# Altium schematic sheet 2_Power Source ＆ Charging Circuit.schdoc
size 441 x 411 mm
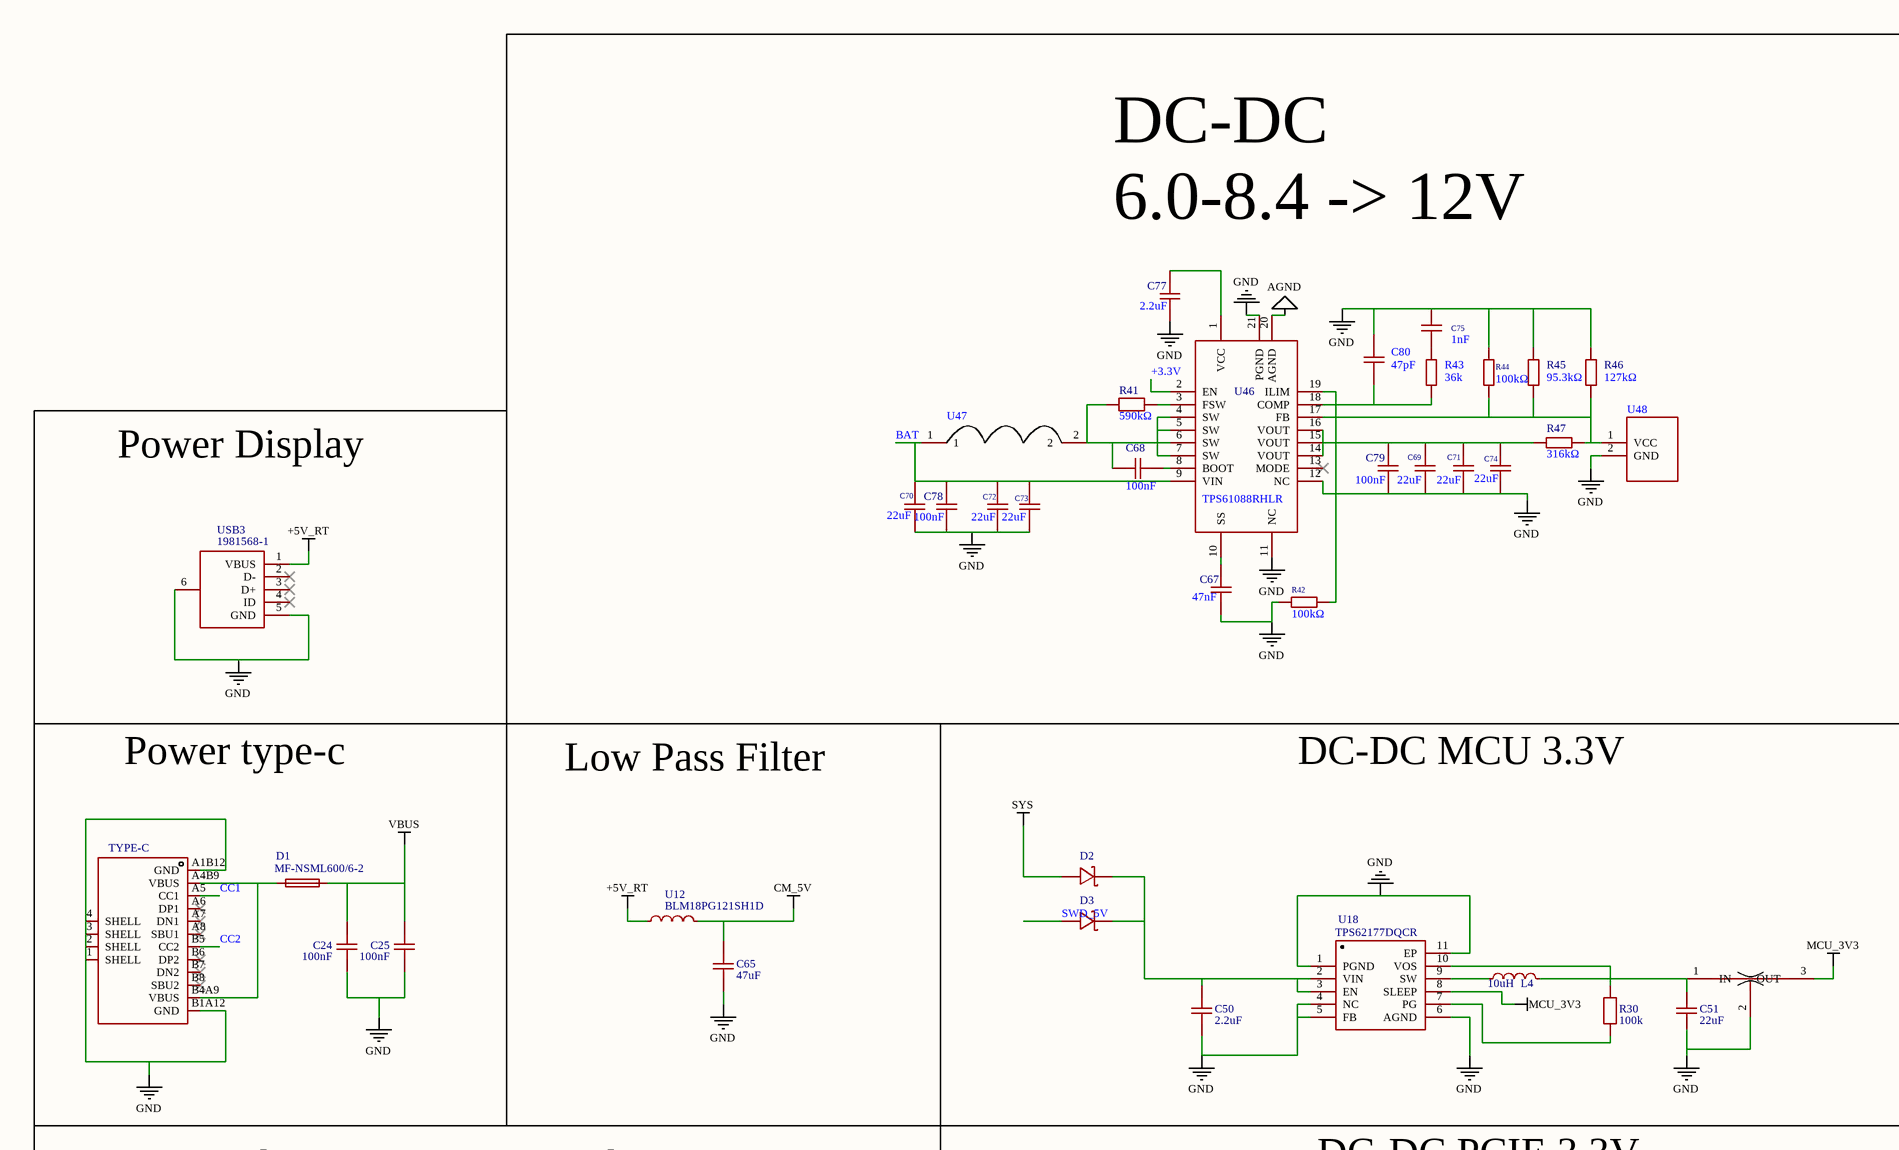
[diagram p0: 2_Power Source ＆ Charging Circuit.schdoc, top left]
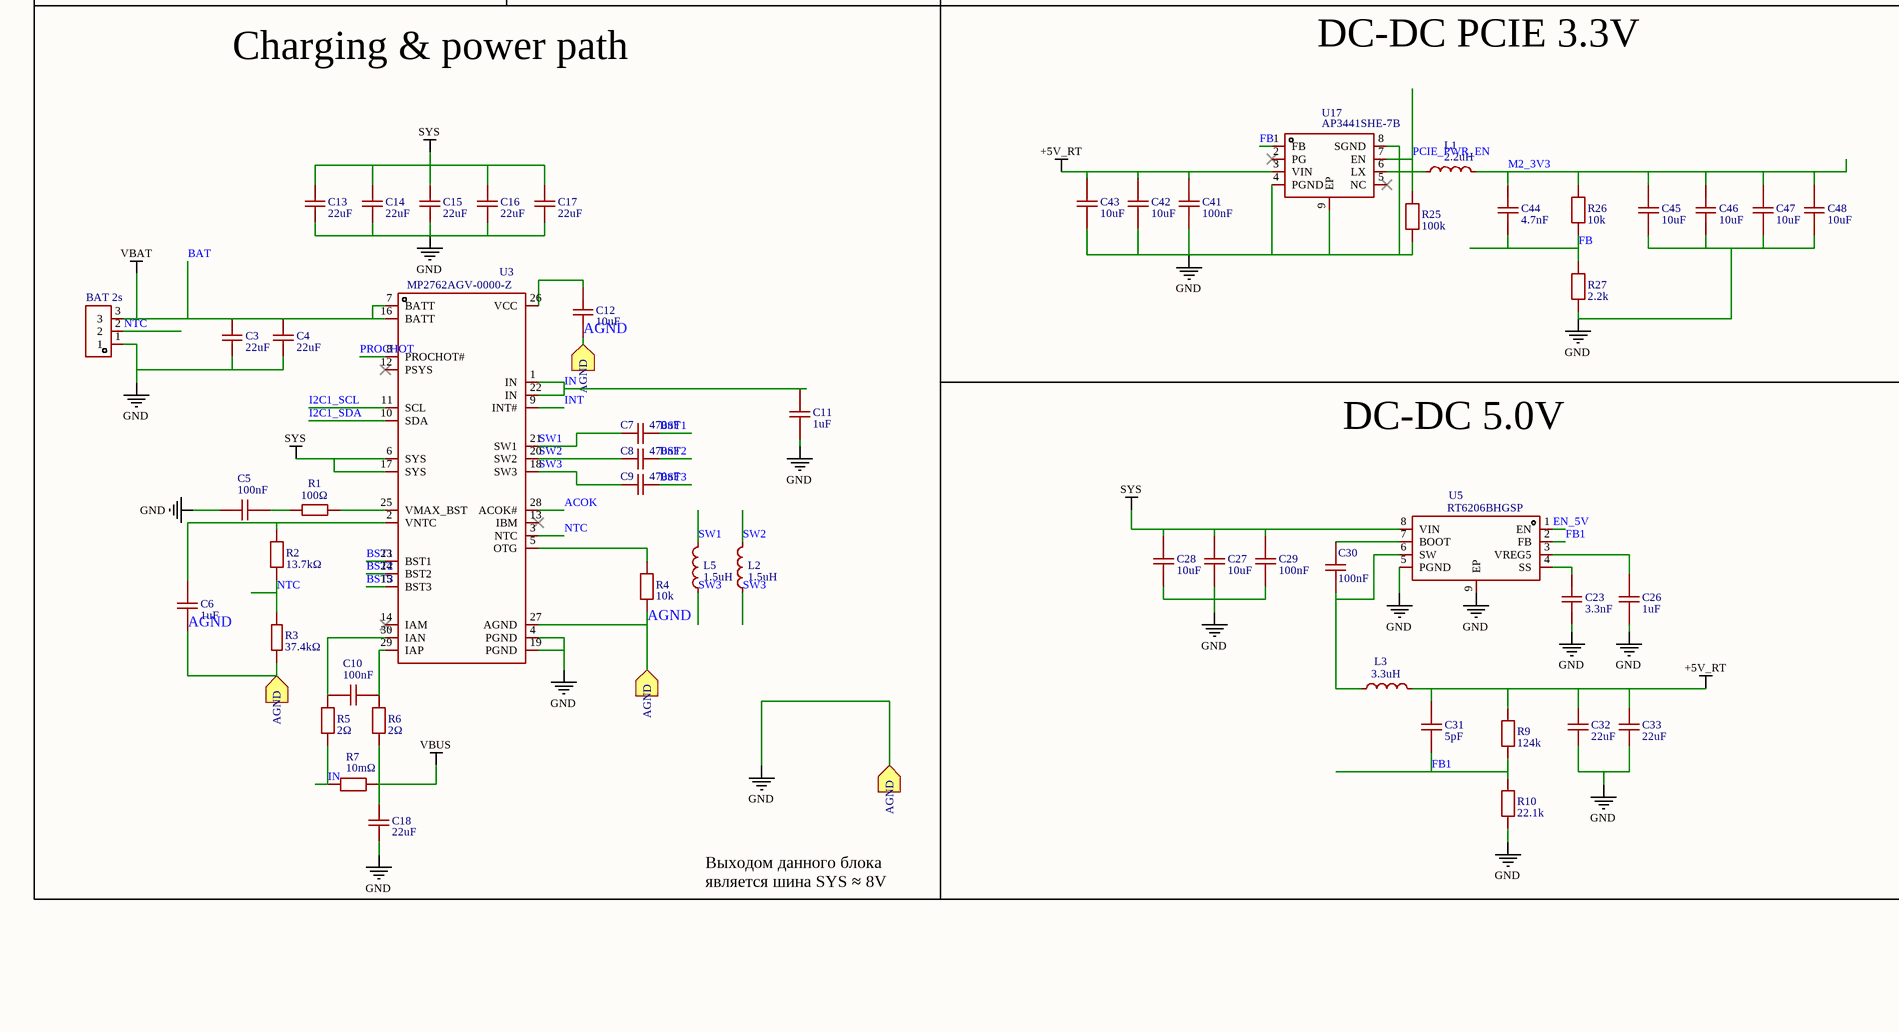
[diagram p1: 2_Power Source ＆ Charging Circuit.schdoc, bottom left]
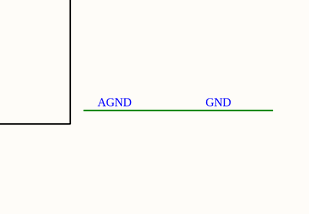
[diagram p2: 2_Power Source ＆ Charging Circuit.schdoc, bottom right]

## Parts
C3  22uF  [C0805]
C4  22uF  [C0805]
C5  100nF  [C0603]
C6  1uF  [C0603]
C7  470nF  [C0603]
C8  470nF  [C0603]
C9  470nF  [C0603]
C10  100nF  [C0603]
C11  1uF  [C0603]
C12  10uF  [C0603]
C13  22uF  [C0805]
C14  22uF  [C0805]
C15  22uF  [C0805]
C16  22uF  [C0805]
C17  22uF  [C0805]
C18  22uF  [C0805]
C23  3.3nF  [C0603]
C24  100nF  [C0603]
C25  100nF  [C0603]
C26  1uF  [C0603]
C27  10uF  [C0603]
C28  10uF  [C0603]
C29  100nF  [C0603]
C30  100nF  [C0603]
C31  5pF  [C0603]
C32  22uF  [C0805]
C33  22uF  [C0805]
C41  100nF  [C0603]
C42  10uF  [C0603]
C43  10uF  [C0603]
C44  4.7nF  [C0603]
C45  10uF  [C0603]
C46  10uF  [C0603]
C47  10uF  [C0603]
C48  10uF  [C0603]
C50  2.2uF  [C0603]
C51  22uF  [C0805]
C63  -  [FILTER-SMD_3P-L1.6-W0.8-L_NFM18CC223R1C3D]  (value not drawn)
C65  47uF  [C0603]
C67  47nF  [C0603]
C68  100nF  [C0603]
C69  22uF  [C0805]
C70  22uF  [C0805]
C71  22uF  [C0805]
C72  22uF  [C0805]
C73  22uF  [C0805]
C74  22uF  [C0805]
C75  1nF  [C0603]
C77  2.2uF  [C0402]
C78  100nF  [C0603]
C79  100nF  [C0603]
C80  47pF  [C0603]
D1  MF-NSML600/6-2  [F1206]
D2  BAT60AE6327HTSA1  [SOD-323_L1.8-W1.3-LS2.5-RD]  (value not drawn)
D3  BAT60AE6327HTSA1  [SOD-323_L1.8-W1.3-LS2.5-RD]  (value not drawn)
L1  2.2uH  [IND-SMD_L3.0-W3.0_IHLP-1212BZ]
L2  1.5uH  [IND-SMD_L5.5-W5.2]
L3  3.3uH  [IND-SMD_L6.5-W6.5_IHLP-2525]
L4  10uH  [IND-SMD_L4.0-W4.0_VLCF4020]
L5  1.5uH  [IND-SMD_L5.5-W5.2]
R1  100Ω  [R0603]
R2  13.7kΩ  [R0603]
R3  37.4kΩ  [R0603]
R4  10k  [R0603]
R5  2Ω  [R0603]
R6  2Ω  [R0603]
R7  10mΩ  [R1206]
R9  124k  [R0603]
R10  22.1k  [R0603]
R25  100k  [R0603]
R26  10k  [R0603]
R27  2.2k  [R0603]
R30  100k  [R0603]
R41  590kΩ  [R0402]
R42  100kΩ  [R0603]
R43  36k  [R0603]
R44  100kΩ  [R0603]
R45  95.3kΩ  [R0603]
R46  127kΩ  [R0603]
R47  316kΩ  [R0603]
U2  BAT 2s  [CONN-TH_XH2.54-3P]
U3  MP2762AGV-0000-Z  [QFN-30_L5.0-W4.0-P0.50-TL_MP2762A]
U5  RT6206BHGSP  [SOP-8_L4.9-W3.9-P1.27-LS6.0-BL-EP-2]
U12  BLM18PG121SH1D  [L0603]
U17  AP3441SHE-7B  [DFN2020-8_L2.0-W2.0-P0.50-BL-EP]
U18  TPS62177DQCR  [WSON-10_L3.0-W2.0-P0.50-BL-EP]
U44  TYPE-C  [USB-C-SMD_TYPE-C16PIN-SHOUHAN]
U46  TPS61088RHLR  [VQFN-20_L4.6-W3.6-P0.50-BL]
U47  (no value)  [CDCSAB0420-1R5M]
U48  (no value)  [DS-201]
USB3  1981568-1  [MICRO-USB-SMD_1981568-1]

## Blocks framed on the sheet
Power Display: USB3
Power type-c: C24 C25 D1 U44
Low Pass Filter: C65 U12
DC-DC MCU 3.3V: C50 C51 C63 D2 D3 L4 R30 U18
Charging & power path: C3-C18 L2 L5 R1-R7 U2 U3
DC-DC PCIE 3.3V: C41-C48 L1 R25-R27 U17
DC-DC 5.0V: C23 C26-C33 L3 R9 R10 U5

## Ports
AGND (in)

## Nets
+5V_RT: C31.2 C32.2 C33.2 C41.2 C42.2 C43.2 L3.2 R9.2 U12.1 U17.3(VIN) USB3.1(VBUS)
AGND: C3.1 C4.1 C5.1 C6.1 C11.1 C12.1 C13.1 C14.1 C15.1 C16.1 C17.1 C18.1 C23.1 C24.1 C25.1 C26.1 C27.1 C28.1 C29.1 C32.1 C33.1 C41.1 C42.1 C43.1 C45.1 C46.1 C47.1 C48.1 C50.1 C51.1 C63.2(GND) C65.1 C67.1 C69.1 C70.1 C71.1 C72.1 C73.1 C74.1 C75.2 C77.1 C78.1 C79.1 C80.1 R3.2 R4.1 R10.1 R25.1 R27.1 R42.1 R44.2 R45.2 R46.2 U2.1 U3.4(PGND) U3.19(PGND) U3.27(AGND) U5.5(PGND) U5.9(EP) U17.4(PGND) U17.8(SGND) U17.9(EP) U18.1(PGND) U18.4(NC) U18.5(FB) U18.6(AGND) U18.11(EP) U44.1(SHELL) U44.2(SHELL) U44.3(SHELL) U44.4(SHELL) U44.A1B12(GND) U44.B1A12(GND) U46.11(NC) U46.12(NC) U46.20(AGND) U46.21(PGND) U48.2(GND) USB3.5(GND) USB3.6(EH) ; port AGND  [also labelled GND]
BAT: C3.2 C4.2 C70.2 C72.2 C73.2 C78.2 U2.3 U3.7(BATT) U3.16(BATT) U46.9(VIN) U47.1  [also labelled VBAT]
CM_5V: C65.2 U12.2
MCU_3V3: C63.3(OUT) U18.8(SLEEP)
SYS: C13.2 C14.2 C15.2 C16.2 C17.2 C27.2 C28.2 C29.2 D2.2(A) U3.6(SYS) U3.17(SYS) U5.8(VIN)
VBUS: C18.2 C24.2 C25.2 D1.2 R6.1 R7.2
+3.3V: U46.2(EN)
ACOK: U3.28(ACOK#)
BST1: C7.2 U3.23(BST1)
BST2: C8.2 U3.24(BST2)
BST3: C9.2 U3.15(BST3)
CC1: U44.A5(CC1)
CC2: U44.B5(CC2)
EN_5V: U5.1(EN)
FB: C44.1 R26.1 R27.2 U17.1(FB)
FB1: C31.1 R9.1 R10.2 U5.2(FB)
I2C1_SCL: U3.11(SCL)
I2C1_SDA: U3.10(SDA)
IN: C11.2 R5.1 R7.1 U3.1(IN) U3.22(IN)
INT: U3.9(INT#)
M2_3V3: C44.2 C45.2 C46.2 C47.2 C48.2 L1.2 R26.2
NTC: R2.1 R3.1 U2.2 U3.3(NTC)
PCIE_PWR_EN: R25.2 U17.7(EN)
PROCHOT: U3.8(PROCHOT#)
SW1: C7.1 L5.2 U3.21(SW1)
SW2: C8.1 L2.2 U3.20(SW2)
SW3: C9.1 L2.1 L5.1 U3.18(SW3)
SWD_5V: D3.2(A)
NetC5_2: C5.2 R1.1
NetC6_2: C6.2 R2.2 U3.2(VNTC)
NetC10_1: C10.1 R5.2 U3.30(IAN)
NetC10_2: C10.2 R6.2 U3.29(IAP)
NetC12_2: C12.2 U3.26(VCC)
NetC23_2: C23.2 U5.4(SS)
NetC26_2: C26.2 U5.3(VREG5)
NetC30_1: C30.1 L3.1 U5.6(SW)
NetC30_2: C30.2 U5.7(BOOT)
NetC50_2: C50.2 D2.1(K) D3.1(K) U18.2(VIN) U18.3(EN)
NetC51_2: C51.2 C63.1(IN) L4.2 R30.2 U18.10(VOS)
NetC67_2: C67.2 U46.10(SS)
NetC68_1: C68.1 R41.1 U46.4(SW) U46.5(SW) U46.6(SW) U46.7(SW) U47.2
NetC68_2: C68.2 U46.8(BOOT)
NetC69_2: C69.2 C71.2 C74.2 C79.2 R47.1 U46.14(VOUT) U46.15(VOUT) U46.16(VOUT)
NetC75_1: C75.1 R43.2
NetC77_2: C77.2 U46.1(VCC)
NetC80_2: C80.2 R43.1 U46.18(COMP)
NetD1_1: D1.1 U44.A4B9(VBUS) U44.B4A9(VBUS)
NetL1_1: L1.1 U17.6(LX)
NetL4_1: L4.1 U18.9(SW)
NetR1_2: R1.2 U3.25(VMAX_BST)
NetR4_2: R4.2 U3.5(OTG)
NetR30_1: R30.1 U18.7(PG)
NetR41_2: R41.2 U46.3(FSW)
NetR42_2: R42.2 U46.19(ILIM)
NetR44_1: R44.1 R45.1 R46.1 R47.2 U46.17(FB) U48.1(VCC)

Not connected (* = marked no-connect by the designer): U3 12(PSYS)* 13(IBM)* 14(IAM)*; U17 2(PG)* 5(NC)*; U44 A6(DP1)* A7(DN1)* A8(SBU1)* B6(DP2)* B7(DN2)* B8(SBU2)*; U46 13(MODE)*; USB3 2(D-)* 3(D+)* 4(ID)*

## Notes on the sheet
- (near C77) DC-DC
  6.0-8.4 -> 12V
- Выходом данного блока
  является шина SYS ≈ 8V

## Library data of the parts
C3 C4 C13-C18 C32 C33 C51 = 22uF: Manufacturer: muRata(村田); Manufacturer Part: GRM21BR61E226ME44L; Convert to PCB: yes; nameAlias: Value
C5 C10 C24 C25 = 100nF: Manufacturer: YAGEO(国巨); Manufacturer Part: CC0603KRX7R0BB104; Convert to PCB: yes; nameAlias: Value; Contributor: LCSC
C6 = 1uF: Manufacturer: muRata(村田); Convert to PCB: yes; nameAlias: Value(F); Contributor: LCEDA_Lib
C7-C9 = 470nF: Manufacturer Part: CL10B474KA8NNNC; Manufacturer: SAMSUNG(三星); Convert to PCB: yes; nameAlias: Value
C11 = 1uF: Manufacturer: muRata(村田); Manufacturer Part: GRM188R61A105KA61D; Convert to PCB: yes; nameAlias: Value
C12 = 10uF: Manufacturer: muRata(村田); Manufacturer Part: GRM188R61A105KA61D; Convert to PCB: yes; nameAlias: Value
C23 = 3.3nF: Convert to PCB: yes; nameAlias: Value(F); Contributor: LCEDA_Lib
C26 = 1uF: Convert to PCB: yes; nameAlias: Value(F); Contributor: LCEDA_Lib
C27 C28 C42 C43 C45-C48 = 10uF: Convert to PCB: yes; nameAlias: Value(F); Contributor: LCEDA_Lib
C29 C30 C41 = 100nF: Convert to PCB: yes; nameAlias: Value(F); Contributor: LCEDA_Lib
C31 = 5pF: Convert to PCB: yes; nameAlias: Value(F); Contributor: LCEDA_Lib
C44 = 4.7nF: Convert to PCB: yes; nameAlias: Value(F); Contributor: LCEDA_Lib
C50 = 2.2uF: Convert to PCB: yes; nameAlias: Value(F); Contributor: LCEDA_Lib
C63 = -: Manufacturer: muRata(村田); Manufacturer Part: NFM18PC104R1C3D; Convert to PCB: yes; nameAlias: Value
C65 = 47uF: Convert to PCB: yes; nameAlias: Value(F); Contributor: LCEDA_Lib
C67 = 06035C473KAT2A: Manufacturer: Kyocera AVX; Add into BOM: yes; Tolerance: ±10%
C68 C78 C79 = CC0603KRX7R9BB104: Manufacturer: YAGEO(国巨); Add into BOM: yes; Tolerance: ±10%; Voltage Rating: 50V; Temperature Coefficient: X7R
C69-C74 = GRM219R61C226ME15L: Manufacturer: muRata(村田); Add into BOM: yes; Tolerance: ±20%
C75 = CC0603KRX7R9BB102: Manufacturer: YAGEO(国巨); Add into BOM: yes; Tolerance: ±10%
C77 = GRM155R61C225KE11D: Manufacturer: muRata(村田); Add into BOM: yes; Tolerance: ±10%; Voltage Rating: 16V; Temperature Coefficient: X5R
C80 = CAP_0603: Symbol: CAP; Convert to PCB: yes
D1 = MF-NSML600/6-2: Manufacturer: BOURNS; Convert to PCB: yes; Contributor: LCSC
D2 D3 = BAT60AE6327HTSA1: Manufacturer: Infineon(英飞凌); Convert to PCB: yes; Contributor: LCSC
L1 = 2.2uH: Manufacturer: VISHAY(威世); Manufacturer Part: IHLP1212BZER2R2M11; Convert to PCB: yes; Contributor: LCSC; nameAlias: Value
L2 L5 = 1.5uH: Manufacturer: VISHAY(威世); Manufacturer Part: IHLP2020CZER2R2M01; Convert to PCB: yes; nameAlias: Value; Contributor: lcsc
L3 = 3.3uH: Manufacturer: VISHAY(威世); Manufacturer Part: IHLP2525CZER3R3M01; Convert to PCB: yes; nameAlias: Value; Contributor: LCSC
L4 = 10uH: Manufacturer: TDK; Manufacturer Part: VLCF4020T-100MR85; Convert to PCB: yes; nameAlias: Value; Contributor: LCSC
R1 = 100Ω: Manufacturer: YAGEO(国巨); Manufacturer Part: AC0603FR-07100RL; Convert to PCB: yes; nameAlias: Value
R2 = 13.7kΩ: Convert to PCB: yes; nameAlias: Value(Ω); Contributor: LCEDA_Lib
R3 = 37.4kΩ: Manufacturer: YAGEO(国巨); Manufacturer Part: RC0603FR-0737K4L; Convert to PCB: yes; nameAlias: Value; Contributor: LCSC
R4 R26 = 10k: Convert to PCB: yes; nameAlias: Value(Ω); Contributor: LCEDA_Lib
R5 R6 = 2Ω: Convert to PCB: yes; nameAlias: Value(Ω); Contributor: LCEDA_Lib
R7 = 10mΩ: Manufacturer: VISHAY(威世); Manufacturer Part: WSL1206R0100FEA; Convert to PCB: yes; Contributor: lcsc; nameAlias: Value
R9 = 124k: Convert to PCB: yes; nameAlias: Value(Ω); Contributor: LCEDA_Lib
R10 = 22.1k: Convert to PCB: yes; nameAlias: Value(Ω); Contributor: LCEDA_Lib
R25 R30 = 100k: Convert to PCB: yes; nameAlias: Value(Ω); Contributor: LCEDA_Lib
R27 = 2.2k: Convert to PCB: yes; nameAlias: Value(Ω); Contributor: LCEDA_Lib
R41 = RC0402FR-07590KL: Manufacturer: YAGEO(国巨); Add into BOM: yes; Tolerance: ±1%; Temperature Coefficient: ±100ppm/℃
R42 R44 = RC0603FR-07100KL: Manufacturer: YAGEO(国巨); Add into BOM: yes; Tolerance: ±1%; Temperature Coefficient: ±100ppm/℃
R43 = Res_0603: Symbol: Res; Convert to PCB: yes
R45 = RC0603FR-0795K3L: Manufacturer: YAGEO(国巨); Add into BOM: yes; Tolerance: ±1%; Temperature Coefficient: ±100ppm/℃
R46 = RC0603FR-07127KL: Manufacturer: YAGEO(国巨); Add into BOM: yes; Tolerance: ±1%; Power(Watts): 100mW; Voltage-Supply(Max): 75V; Temperature Coefficient: ±100ppm/℃
R47 = RC0603FR-07316KL: Manufacturer: YAGEO(国巨); Add into BOM: yes; Tolerance: ±1%; Temperature Coefficient: ±100ppm/℃
U2 = BAT 2s: Manufacturer: null; Manufacturer Part: XH2.54-3P 直插; Convert to PCB: yes; Contributor: LCSC
U3 = MP2762AGV-0000-Z: Manufacturer: MPS(芯源); Convert to PCB: yes; Contributor: lcsc
U5 = RT6206BHGSP: Manufacturer: RICHTEK(立锜); Convert to PCB: yes; Contributor: LCSC
U12 = BLM18PG121SH1D: Manufacturer: muRata(村田); Convert to PCB: yes; Contributor: LCSC
U17 = AP3441SHE-7B: Manufacturer: DIODES(美台); Convert to PCB: yes; Contributor: LCSC
U18 = TPS62177DQCR: Manufacturer: TI(德州仪器); Convert to PCB: yes
U44 = TYPE-C: Manufacturer: null; Manufacturer Part: Type-C 母座单排16P四脚插板; Convert to PCB: yes; Contributor: LCSC
U46 = TPS61088RHLR: Manufacturer: TI(德州仪器); Add into BOM: yes; Function: Boost type; Output Type: Adjustable; Input Voltage: 2.7V~12V; Output Voltage: 4.5V~12.6V; Output Current: 10A; Switching Frequency: 200kHz~2.2MHz; Number of Outputs: 1; Topology: Boost; Switch tube (built-in/external): Built-in
U47 = CDCSAB0420-1R5M: Add into BOM: yes
U48 = DS-201: Add into BOM: yes
USB3 = 1981568-1: Manufacturer: TE Connectivity(泰科电子); Convert to PCB: yes; Contributor: LCSC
